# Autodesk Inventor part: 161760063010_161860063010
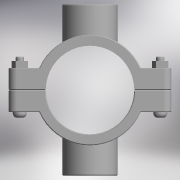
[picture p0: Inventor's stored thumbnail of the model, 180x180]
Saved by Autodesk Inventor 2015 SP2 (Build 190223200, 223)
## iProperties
Created: 2017-05
Part Number: 161760063010_161860063010
Material: Generic
Description: PLASSON DOUBLE SADDLE 63-1"
Document SubType Name: Modeling
Designer: KIM
Density: 1 g/cm^3
Appearance: Default
Author: KIM
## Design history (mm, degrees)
derived "16176.ipt"
feature "Solid1::16176.ipt"
feature "Solid2::16176.ipt"
tag "TaggingFeature1"
body "Solid1"
body "Solid2"
other parameters: "d0" = 78.75, "d1" = 116, "d2" = 31.5, "d3" = 63, "d4" = 84, "d5" = 0, "d6" = 5.8, "d7" = 116, "d8" = 0.1, "d10" = 0, "d11" = 0.63, "d20" = 0.63, "d23" = 0.63, "d37" = 8, "d38" = 39.5, "d39" = 0, "d40" = 3, "d41" = 5, "d42" = 0, "d43" = 6, "d44" = 3, "d45" = 0, "d46" = 0.63, "d52" = 30.291, "d53" = 21, "d54" = 0, "d55" = 25, "d57" = 0, "d58" = 68.04, "d60" = 0, "d63" = 8, "d66" = 68, "d67" = 122, "d68" = 39.3783, "d69" = 30.291, "d70" = 21, "d71" = 0, "d72" = 25, "d74" = 0, "d75" = 0.63, "d_" = 63, "B_" = 25, "G_" = 30.291, "A_" = 61, "L_" = 116, "L_1" = 84, "l_2" = 21
